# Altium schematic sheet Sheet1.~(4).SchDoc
size A; SheetNumber: 1; SheetTotal: 1
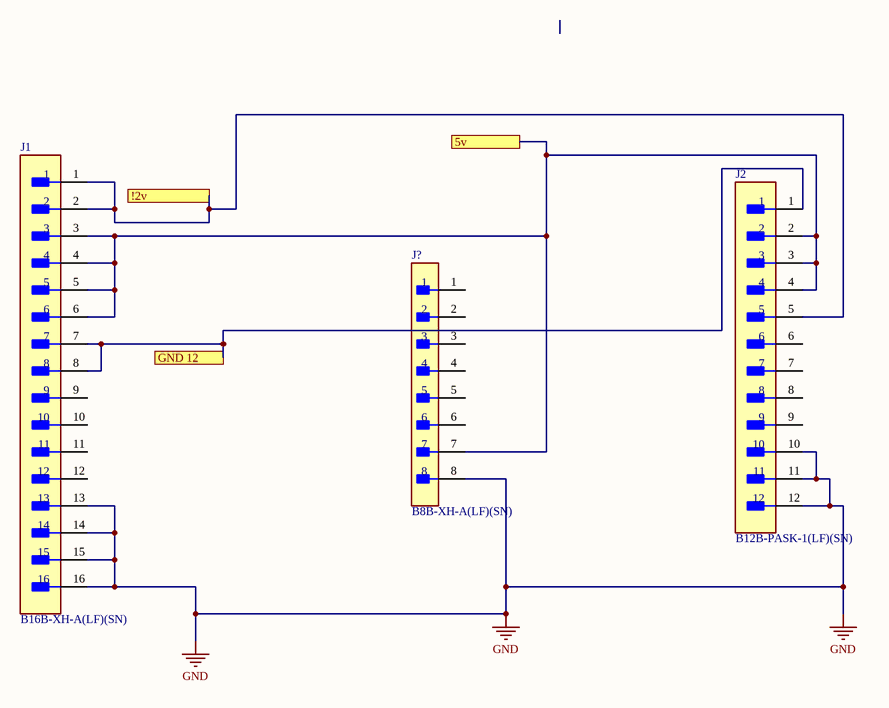
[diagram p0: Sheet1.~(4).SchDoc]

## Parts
J1  B16B-XH-A(LF)(SN)  [FP-B16B-XH-A_LF_SN-MFG]
J2  B12B-PASK-1(LF)(SN)  [FP-B12B-PASK-1_LF_SN-MFG]
J?  B8B-XH-A(LF)(SN)  [FP-B8B-XH-A_LF_SN-MFG]

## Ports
5v, !2v, GND 12

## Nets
GND: J1.13 J1.14 J1.15 J1.16 J2.10 J2.11 J2.12 J?.8
5v: J1.3 J1.4 J1.5 J1.6 J2.2 J2.3 J2.4 J?.7 ; port 5v
!2v: J1.1 J1.2 J2.5 ; port !2v
GND 12: J1.7 J1.8 J2.1 ; port GND 12

Not connected (* = marked no-connect by the designer): J1 9 10 11 12; J2 6 7 8 9; J? 1 2 3 4 5 6

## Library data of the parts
J1 = CMP-17439-000590-1: CONN HEADER VERT 16POS 2.5MM; Contact Resistance: 20mR; Number of Contacts: 16; Gender: Male; Pitch: 0.098inch; Connector Type: Male Pin; Max Voltage Rating (AC): 250V; Max Current Rating: 3A
J2 = CMP-17439-000523-1: CONN HEADER VERT 12POS 2MM; Voltage Rating: 250V; Number of Positions: 12; Mated Stacking Heights: 14.9mm; Current Rating: 3A
J? = CMP-17438-000015-1: CONN HEADER VERT 8POS 2.5MM; Voltage Rating (AC): 250V; Insulation Resistance: 1GR; Connector Type: Male Pin; Max Current Rating: 3A; Wire/Cable Gauge: 22AWG; Number of Contacts: 8; Contact Resistance: 20mR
